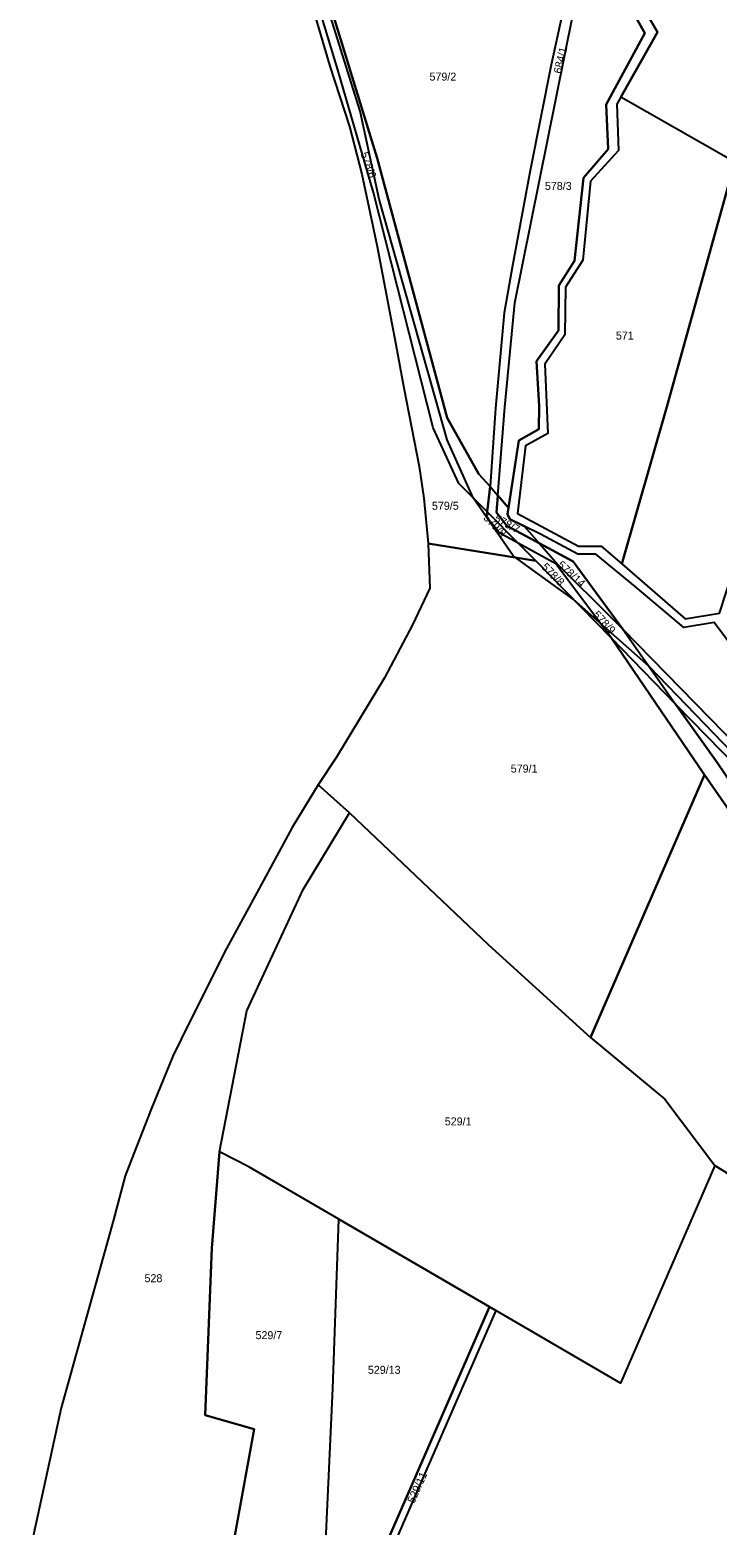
# Model space of a CAD drawing. Extents: x -629983 to -626385, y -1072828 to -1067897.
# Drawn here: x -627841 to -627583, y -1069550 to -1068990 of the extents above; entities that cross this region are included whole.
import ezdxf

# ---------------------------------------------------------------- set-up
doc = ezdxf.new("R2010")
doc.units = 0
for name, color, linetype in [('Lesy', 7, 'Continuous'), ('Parcela nároku', 7, 'Continuous'), ('Parcelní číslo', 7, 'Continuous'), ('Plocha PÚ', 7, 'Continuous'), ('Převzatý obvod_Opočno', 7, 'Continuous'), ('voda', 7, 'Continuous')]:
    doc.layers.add(name, color=color, linetype=linetype)

msp = doc.modelspace()

# ---------------------------------------------------------------- linework, layer by layer
at = {"layer": 'Lesy'}
msp.add_line((-627587.87, -1069269.14), (-627630.67, -1069367.65), dxfattribs=at)
at = {"layer": 'Parcela nároku'}
for points in [[(-627663.03, -1069095.94), (-627666.3, -1069131.69), (-627668.24, -1069161.01), (-627665.38, -1069164.4), (-627662.79, -1069131.38), (-627658.99, -1069092.21), (-627637.25, -1068984.36), (-627630.77, -1068955.68), (-627623.72, -1068922.54), (-627608.67, -1068853.79), (-627612.67, -1068853.16), (-627627.23, -1068920.63), (-627633.84, -1068950.3), (-627645.34, -1069002.98), (-627653.33, -1069042.58), (-627660.07, -1069078.95)], [(-627541.67, -1068910.56), (-627536.66, -1068911.49), (-627578.96, -1069038.13), (-627619.33, -1069015.15), (-627605.58, -1068990.76), (-627611.83, -1068980.04), (-627603.02, -1068974.61), (-627603.36, -1068962.42), (-627603.37, -1068948.03), (-627594.26, -1068943.85), (-627593.58, -1068939.95), (-627599.72, -1068932.52), (-627593.42, -1068929.74), (-627589.61, -1068912.68), (-627582.29, -1068903.91), (-627585.58, -1068896.11), (-627570.08, -1068877.27), (-627576.3, -1068868.62), (-627578.92, -1068858.11), (-627561.45, -1068858.96), (-627546.19, -1068860.81), (-627542.18, -1068861.77)], [(-627680.68, -1068893.1), (-627673.72, -1068896.3), (-627627.23, -1068920.63), (-627633.84, -1068950.3), (-627645.34, -1069002.98), (-627653.33, -1069042.58), (-627660.07, -1069078.95), (-627663.03, -1069095.94), (-627666.3, -1069131.69), (-627668.24, -1069161.01), (-627672.57, -1069156.47), (-627684.37, -1069135.35), (-627710.62, -1069037.96), (-627744.49, -1068927.66), (-627728.98, -1068923.71)], [(-627672.57, -1069156.47), (-627668.24, -1069161.01), (-627669.41, -1069170.58), (-627679.98, -1069159.96), (-627689.67, -1069139.02), (-627711.97, -1069050.84), (-627725.33, -1069004.9), (-627748.35, -1068928.94), (-627744.49, -1068927.66), (-627710.62, -1069037.96), (-627684.37, -1069135.35)], [(-627662.79, -1069131.38), (-627658.99, -1069092.21), (-627637.25, -1068984.36), (-627630.77, -1068955.68), (-627623.72, -1068922.54), (-627607.72, -1068930.75), (-627597.33, -1068941.88), (-627606.91, -1068946.03), (-627606.23, -1068958.26), (-627606.09, -1068972.77), (-627617.12, -1068979.03), (-627610.22, -1068991.12), (-627624.74, -1069017.84), (-627624, -1069034.55), (-627633.33, -1069045.36), (-627636.7, -1069076.5), (-627642.58, -1069085.74), (-627642.61, -1069102.64), (-627650.94, -1069114.12), (-627649.85, -1069130.94), (-627649.97, -1069139.58), (-627657.58, -1069143.79), (-627661.43, -1069169.08), (-627665.38, -1069164.4)], [(-627669.41, -1069170.58), (-627679.98, -1069159.96), (-627689.67, -1069139.02), (-627711.97, -1069050.84), (-627725.33, -1069004.9), (-627748.35, -1068928.94), (-627750.88, -1068929.78), (-627737.89, -1068971.16), (-627728.35, -1069003.46), (-627721.01, -1069026.12), (-627716.42, -1069043.96), (-627710.61, -1069071.05), (-627703.7, -1069107.81), (-627700.64, -1069124.1), (-627694.93, -1069153.57), (-627693.1, -1069165.44), (-627691.51, -1069182.4), (-627651.18, -1069188.9), (-627657.71, -1069182.34), (-627664.84, -1069178.41), (-627669.64, -1069172.47)], [(-627630.68, -1069046.56), (-627633.57, -1069076.26), (-627640.03, -1069086.3), (-627640.24, -1069104.24), (-627647.79, -1069115.17), (-627646.65, -1069141.16), (-627654.96, -1069145.76), (-627657.96, -1069171.17), (-627635.13, -1069183.43), (-627626.6, -1069183.39), (-627618.88, -1069190.06), (-627601.99, -1069131.19), (-627576.57, -1069039.46), (-627578.96, -1069038.13), (-627619.33, -1069015.15), (-627620.79, -1069017.75), (-627620.11, -1069035.1)], [(-627576.57, -1069039.46), (-627601.99, -1069131.19), (-627618.88, -1069190.06), (-627595.18, -1069210.65), (-627582.28, -1069208.53), (-627581.46, -1069205.86), (-627580.43, -1069202.71), (-627569.68, -1069170.14), (-627535.1, -1069051.69)], [(-627622.58, -1069210.52), (-627618.57, -1069214.56), (-627598.81, -1069242.61), (-627622.78, -1069217.95), (-627643.64, -1069190.09), (-627657.71, -1069182.34), (-627669.41, -1069170.58), (-627668.24, -1069161.01), (-627665.38, -1069164.4), (-627665.93, -1069170.85), (-627661.98, -1069175.8), (-627649.85, -1069182.33), (-627642.84, -1069190.3)], [(-627655.52, -1069175.88), (-627649.85, -1069182.33), (-627661.98, -1069175.8), (-627665.93, -1069170.85), (-627665.38, -1069164.4), (-627661.43, -1069169.08), (-627661.71, -1069171.47), (-627660.9, -1069173.25)], [(-627669.64, -1069172.47), (-627669.41, -1069170.58), (-627657.71, -1069182.34), (-627664.84, -1069178.41)], [(-627707.86, -1069232.76), (-627725.92, -1069262.56), (-627732.73, -1069272.86), (-627721.03, -1069283.43), (-627669, -1069332.77), (-627630.67, -1069367.65), (-627587.87, -1069269.14), (-627622.78, -1069217.95), (-627651.18, -1069188.9), (-627691.51, -1069182.4), (-627690.85, -1069199.14), (-627697.36, -1069212.96)], [(-627622.78, -1069217.95), (-627643.64, -1069190.09), (-627657.71, -1069182.34), (-627651.18, -1069188.9)], [(-627618.57, -1069214.56), (-627637.2, -1069189.14), (-627649.85, -1069182.33), (-627642.84, -1069190.3), (-627622.58, -1069210.52)], [(-627583.15, -1069264.51), (-627598.81, -1069242.61), (-627622.78, -1069217.95), (-627587.87, -1069269.14), (-627556.92, -1069313.71), (-627469.62, -1069440.57), (-627454.33, -1069455.51), (-627442.87, -1069461.88), (-627440.52, -1069456.67), (-627453.31, -1069449.31), (-627463.77, -1069438.44), (-627548.25, -1069316.09)], [(-627324.81, -1069488.6), (-627339.13, -1069480.44), (-627379.75, -1069454.55), (-627515.4, -1069319.93), (-627618.57, -1069214.56), (-627598.81, -1069242.61), (-627517.7, -1069325.48), (-627383, -1069459.06), (-627347.15, -1069482.18), (-627343.99, -1069484.22), (-627337.43, -1069488.19), (-627332.48, -1069490.93)], [(-627517.7, -1069325.48), (-627598.81, -1069242.61), (-627583.15, -1069264.51), (-627548.25, -1069316.09), (-627463.77, -1069438.44), (-627453.31, -1069449.31), (-627440.52, -1069456.67), (-627413.75, -1069471.16), (-627367.69, -1069489.87), (-627345.93, -1069493.32), (-627347.15, -1069482.18), (-627383, -1069459.06)], [(-627556.92, -1069313.71), (-627587.87, -1069269.14), (-627630.67, -1069367.65), (-627602.8, -1069390.7), (-627584.07, -1069415.57), (-627532.45, -1069447.67), (-627450.43, -1069478.79), (-627442.87, -1069461.88), (-627454.33, -1069455.51), (-627469.62, -1069440.57)], [(-627829.14, -1069506.38), (-627840.86, -1069560.25), (-627838.63, -1069560.46), (-627794.31, -1069565.81), (-627767.42, -1069572.88), (-627766.78, -1069569.38), (-627756.76, -1069514.46), (-627775.13, -1069509.21), (-627772.67, -1069446.6), (-627769.72, -1069410.4), (-627759.48, -1069357.61), (-627738.4, -1069312.13), (-627721.03, -1069283.43), (-627732.73, -1069272.86), (-627742.48, -1069288.93), (-627754.94, -1069311.74), (-627767.18, -1069334.28), (-627781.05, -1069361.9), (-627787.25, -1069374.64), (-627795.42, -1069394.51), (-627801.9, -1069411.02), (-627805.08, -1069419.45), (-627809.45, -1069435.93), (-627817.47, -1069464.72)], [(-627630.67, -1069367.65), (-627602.8, -1069390.7), (-627584.07, -1069415.57), (-627619.46, -1069497.12), (-627666.16, -1069469.88), (-627668.46, -1069468.54), (-627725.05, -1069435.63), (-627758.81, -1069416.03), (-627769.72, -1069410.4), (-627759.48, -1069357.61), (-627738.4, -1069312.13), (-627721.03, -1069283.43), (-627669, -1069332.77)], [(-627756.76, -1069514.46), (-627766.78, -1069569.38), (-627731.06, -1069580.72), (-627727.3, -1069499.18), (-627725.05, -1069435.63), (-627758.81, -1069416.03), (-627769.72, -1069410.4), (-627772.67, -1069446.6), (-627775.13, -1069509.21)], [(-627387.95, -1069506.5), (-627392.29, -1069497.12), (-627417.27, -1069492.05), (-627450.43, -1069478.79), (-627532.45, -1069447.67), (-627584.07, -1069415.57), (-627619.46, -1069497.12), (-627666.16, -1069469.88), (-627716.51, -1069585.55), (-627605.55, -1069622.32), (-627574.69, -1069633.25), (-627551.87, -1069641.76), (-627517.96, -1069653.42), (-627480.65, -1069548.74), (-627453.72, -1069486.59), (-627426.1, -1069499.39)], [(-627731.06, -1069580.72), (-627727.3, -1069499.18), (-627725.05, -1069435.63), (-627668.46, -1069468.54), (-627719.14, -1069584.68)], [(-627668.46, -1069468.54), (-627666.16, -1069469.88), (-627716.51, -1069585.55), (-627719.14, -1069584.68)]]:
    msp.add_lwpolyline(points, close=True, dxfattribs=at)
for points in [[(-627573.99, -1069225.75), (-627584.33, -1069212.03), (-627595.68, -1069213.95), (-627613.9, -1069198.56), (-627628.65, -1069186.36), (-627635.43, -1069186.41), (-627649.36, -1069178.98), (-627655.52, -1069175.88), (-627660.9, -1069173.25), (-627661.71, -1069171.47), (-627661.43, -1069169.08), (-627657.58, -1069143.79), (-627649.97, -1069139.58), (-627649.85, -1069130.94), (-627650.94, -1069114.12), (-627642.61, -1069102.64), (-627642.58, -1069085.74), (-627636.7, -1069076.5), (-627633.33, -1069045.36), (-627624, -1069034.55), (-627624.74, -1069017.84), (-627610.22, -1068991.12), (-627617.12, -1068979.03)], [(-627611.83, -1068980.04), (-627605.58, -1068990.76), (-627619.33, -1069015.15), (-627620.79, -1069017.75), (-627620.11, -1069035.1), (-627630.68, -1069046.56), (-627633.57, -1069076.26), (-627640.03, -1069086.3), (-627640.24, -1069104.24), (-627647.79, -1069115.17), (-627646.65, -1069141.16), (-627654.96, -1069145.76), (-627657.96, -1069171.17), (-627635.13, -1069183.43), (-627626.6, -1069183.39), (-627618.88, -1069190.06), (-627595.18, -1069210.65), (-627582.28, -1069208.53)], [(-627573.99, -1069225.75), (-627584.33, -1069212.03), (-627595.68, -1069213.95), (-627613.9, -1069198.56), (-627628.65, -1069186.36), (-627635.43, -1069186.41), (-627649.36, -1069178.98), (-627655.52, -1069175.88), (-627649.85, -1069182.33), (-627637.2, -1069189.14), (-627618.57, -1069214.56), (-627515.4, -1069319.93)]]:
    msp.add_lwpolyline(points, dxfattribs=at)
at = {"layer": 'Plocha PÚ'}
msp.add_lwpolyline([(-627737.89, -1068971.16), (-627728.35, -1069003.46), (-627721.01, -1069026.12), (-627716.42, -1069043.96), (-627710.61, -1069071.05), (-627703.7, -1069107.81), (-627700.64, -1069124.1), (-627694.93, -1069153.57), (-627693.1, -1069165.44), (-627691.51, -1069182.4), (-627690.85, -1069199.14), (-627697.36, -1069212.96), (-627707.86, -1069232.76), (-627725.92, -1069262.56), (-627732.73, -1069272.86), (-627742.48, -1069288.93), (-627754.94, -1069311.74), (-627767.18, -1069334.28), (-627781.05, -1069361.9), (-627787.25, -1069374.64), (-627795.42, -1069394.51), (-627801.9, -1069411.02), (-627805.08, -1069419.45), (-627809.45, -1069435.93), (-627817.47, -1069464.72), (-627829.14, -1069506.38), (-627840.86, -1069560.25)], dxfattribs=at)
at = {"layer": 'Převzatý obvod_Opočno'}
msp.add_lwpolyline([(-627737.89, -1068971.16), (-627728.35, -1069003.46), (-627721.01, -1069026.12), (-627716.42, -1069043.96), (-627710.61, -1069071.05), (-627703.7, -1069107.81), (-627700.64, -1069124.1), (-627694.93, -1069153.57), (-627693.1, -1069165.44), (-627691.51, -1069182.4), (-627690.85, -1069199.14), (-627697.36, -1069212.96), (-627707.86, -1069232.76), (-627725.92, -1069262.56), (-627732.73, -1069272.86), (-627742.48, -1069288.93), (-627754.94, -1069311.74), (-627767.18, -1069334.28), (-627781.05, -1069361.9), (-627787.25, -1069374.64), (-627795.42, -1069394.51), (-627801.9, -1069411.02), (-627805.08, -1069419.45), (-627809.45, -1069435.93), (-627817.47, -1069464.72), (-627829.14, -1069506.38), (-627840.86, -1069560.25)], dxfattribs=at)
at = {"layer": 'voda'}
for points in [[(-627608.69, -1069228.58), (-627636.98, -1069203.42), (-627659.65, -1069186.99), (-627674.7, -1069165.27), (-627684.43, -1069143.51), (-627696.42, -1069101.03), (-627709.87, -1069053.38), (-627717.07, -1069020.38), (-627737.92, -1068953.69), (-627746.42, -1068928.3), (-627753.26, -1068905.86)], [(-627608.69, -1069228.58), (-627567.33, -1069271.37), (-627536.18, -1069303.59), (-627504.31, -1069334.27), (-627485.76, -1069353.94), (-627464.97, -1069374.06), (-627447.22, -1069392.83), (-627416.71, -1069421.47), (-627386.71, -1069452.38), (-627377.38, -1069459.57), (-627356.25, -1069473.06), (-627328.64, -1069489.76), (-627308.58, -1069501.31), (-627278, -1069518.91), (-627267.24, -1069526.16), (-627251.07, -1069535.67), (-627238.49, -1069545.79), (-627221.22, -1069559.68), (-627209.33, -1069569.24), (-627201.32, -1069574.3)]]:
    msp.add_lwpolyline(points, dxfattribs=at)

# ---------------------------------------------------------------- texts
at = {"layer": 'Parcelní číslo'}
for s, rotation, p in [('684/1', 76.4761, (-627641.68, -1069006.5)), ('578/6', 289.2156, (-627716.94, -1069036.25)), ('579/8', 313.9423, (-627671.02, -1069173.07)), ('578/7', 331.7101, (-627667.04, -1069173.97)), ('578/8', 314.5693, (-627649.28, -1069191.49)), ('578/14', 317.5216, (-627643.31, -1069190.81)), ('578/9', 313.041, (-627629.95, -1069209.33)), ('529/11', 66.0243, (-627696.76, -1069542.46))]:
    msp.add_text(s, height=3, rotation=rotation, dxfattribs=at).set_placement(p)
for s, p in [('579/2', (-627691.02, -1069008.91)), ('578/3', (-627647.76, -1069049.89)), ('571', (-627621.14, -1069105.96)), ('579/5', (-627690.1, -1069169.78)), ('579/1', (-627660.56, -1069268.3)), ('529/1', (-627685.3, -1069400.54)), ('528', (-627797.89, -1069459.32)), ('529/7', (-627756.26, -1069480.67)), ('529/13', (-627714.13, -1069493.66))]:
    msp.add_text(s, height=3, dxfattribs=at).set_placement(p)

doc.saveas('drawing.dxf')
